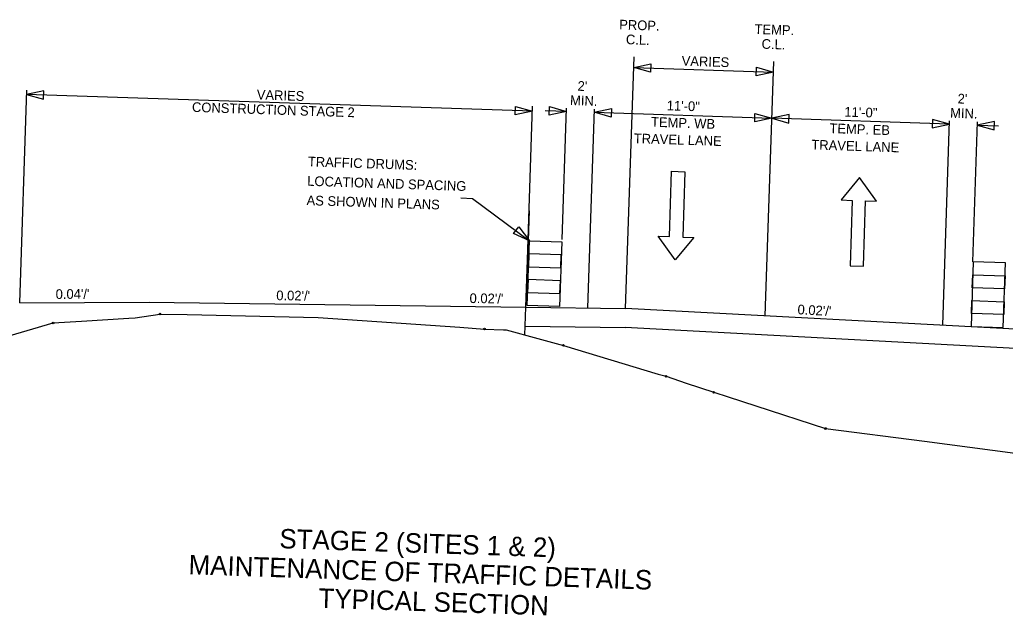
# Model space of a CAD drawing. Extents: x 977258 to 978774, y 1525946 to 1526932.
# Drawn here: x 977645 to 978255, y 1526544 to 1526912 of the extents above; entities that cross this region are included whole.
import ezdxf

# ---------------------------------------------------------------- set-up
doc = ezdxf.new("R2010")
doc.units = 0
for name, color, linetype in [('B_border', 7, 'Continuous'), ('B_County and Route', 7, 'Continuous'), ('B_Preliminary', 7, 'Continuous'), ('B_Print_Date_Text', 7, 'Continuous'), ('B_Title Text', 7, 'Continuous'), ('Default', 7, 'Continuous'), ('R_Border', 7, 'Continuous'), ('R_MOT', 7, 'Continuous'), ('STAMP_PP', 7, 'Continuous')]:
    doc.layers.add(name, color=color, linetype=linetype)

msp = doc.modelspace()

# ---------------------------------------------------------------- linework, layer by layer
at = {"layer": 'B_border'}
for centre in [(977731.73, 1526730.1), (977665.58, 1526724.58), (977932.64, 1526720.78), (977981.46, 1526710.71), (978045.03, 1526691.56), (978074.48, 1526681.68), (978143.72, 1526659.23)]:
    msp.add_circle(centre, 0.5, dxfattribs=at)
at = {"layer": 'B_County and Route'}
for p, q in [((978019.99, 1526733.59), (978025.19, 1526889.28)), ((978106.44, 1526728.97), (978111.69, 1526886.4))]:
    msp.add_line(p, q, dxfattribs=at)
at = {"layer": 'B_Preliminary'}
msp.add_lwpolyline([(977258.38, 1526671.55), (977476.71, 1526670.18), (977576.91, 1526698.71), (977584.62, 1526700.89), (977590.5, 1526702.57), (977665.58, 1526724.58), (977683.24, 1526725.62), (977712.46, 1526727.47), (977716.28, 1526727.8), (977731.73, 1526730.1), (977748.57, 1526729.75), (977829.7, 1526727.99), (977917.45, 1526721.89), (977932.64, 1526720.78), (977944.35, 1526720.32), (977945.99, 1526720.26), (977965.72, 1526714.93), (977981.46, 1526710.71), (978040.15, 1526692.86), (978045.03, 1526691.56), (978057.39, 1526687.35), (978143.72, 1526659.23), (978205.08, 1526651.49), (978261.1, 1526644)], dxfattribs=at)
at = {"layer": 'B_Print_Date_Text'}
for p, q in [((977644.9, 1526736.99), (977724.96, 1526737.52)), ((977724.96, 1526737.52), (977958.24, 1526734.41)), ((977957.66, 1526717.11), (977958.24, 1526734.41)), ((977958.24, 1526734.41), (978019.99, 1526733.59)), ((978314.63, 1526717.86), (978019.99, 1526733.59)), ((977957.84, 1526722.48), (978019.6, 1526721.66)), ((978464.53, 1526697.9), (978019.6, 1526721.66))]:
    msp.add_line(p, q, dxfattribs=at)
at = {"layer": 'B_Title Text'}
for p, q in [((977959.22, 1526763.88), (977960.22, 1526793.85)), ((977960.22, 1526793.85), (977959.41, 1526769.48))]:
    msp.add_line(p, q, dxfattribs=at)
at = {"layer": 'Default'}
for points in [[(978062.22, 1526777.51), (978050.75, 1526763.6), (978040.23, 1526778.24), (978047.1, 1526778.01), (978048.45, 1526818.45), (978056.7, 1526818.17), (978055.35, 1526777.74)], [(978175.36, 1526799.93), (978164.84, 1526814.57), (978153.37, 1526800.66), (978160.24, 1526800.43), (978158.89, 1526760), (978167.14, 1526759.72), (978168.48, 1526800.16)]]:
    msp.add_lwpolyline(points, close=True, dxfattribs=at)
at = {"layer": 'R_MOT'}
for points in [[(977979.06, 1526734.71), (977959.07, 1526735.38), (977960.41, 1526775.36), (977980.4, 1526774.69)], [(977980.13, 1526766.69), (977960.14, 1526767.36), (977959.87, 1526759.37), (977979.86, 1526758.7)], [(978233.79, 1526722.41), (978253.78, 1526721.74), (978255.12, 1526761.72), (978235.13, 1526762.38)], [(977979.6, 1526750.7), (977959.61, 1526751.37), (977959.34, 1526743.37), (977979.33, 1526742.71)], [(978234.86, 1526754.39), (978254.85, 1526753.72), (978254.58, 1526745.73), (978234.59, 1526746.39)], [(978234.33, 1526738.4), (978254.32, 1526737.73), (978254.05, 1526729.74), (978234.06, 1526730.4)]]:
    msp.add_lwpolyline(points, close=True, dxfattribs=at)
at = {"layer": 'STAMP_PP'}
for p, q in [((978024.97, 1526882.68), (978111.47, 1526879.8)), ((977644.9, 1526736.99), (977649.29, 1526868.65)), ((977962.28, 1526855.57), (977649.2, 1526866.01)), ((977983.37, 1526855.48), (977970.14, 1526855.92)), ((977980.73, 1526776.24), (977983.44, 1526857.51)), ((977996.55, 1526733.9), (978000.65, 1526856.93)), ((978000.58, 1526854.91), (978110.52, 1526851.24)), ((978220.46, 1526847.57), (978110.52, 1526851.24)), ((978216.31, 1526723.11), (978220.53, 1526849.6)), ((978234.85, 1526762.39), (978237.74, 1526849.03)), ((978237.67, 1526847), (978250.9, 1526846.56)), ((977918, 1526801.91), (977925.21, 1526801.67)), ((977925.21, 1526801.67), (977960.41, 1526775.36))]:
    msp.add_line(p, q, dxfattribs=at)
for points in [[(978035.43, 1526879.69), (978024.97, 1526882.68), (978035.61, 1526884.97)], [(978101.01, 1526882.79), (978111.47, 1526879.8), (978100.83, 1526877.51)], [(977659.84, 1526868.3), (977649.2, 1526866.01), (977659.67, 1526863.02)], [(977951.81, 1526858.56), (977962.28, 1526855.57), (977951.64, 1526853.29)], [(977972.91, 1526858.47), (977983.37, 1526855.48), (977972.73, 1526853.19)], [(978011.05, 1526851.92), (978000.58, 1526854.91), (978011.22, 1526857.19)], [(978100.05, 1526854.23), (978110.52, 1526851.24), (978099.88, 1526848.95)], [(978121.16, 1526853.53), (978110.52, 1526851.24), (978120.99, 1526848.25)], [(978209.82, 1526845.29), (978220.46, 1526847.57), (978209.99, 1526850.57)], [(978248.31, 1526849.29), (978237.67, 1526847), (978248.13, 1526844.01)], [(977953.83, 1526784.03), (977960.41, 1526775.36), (977950.52, 1526779.91)]]:
    msp.add_lwpolyline(points, close=True, dxfattribs=at)
msp.add_lwpolyline([(977958.24, 1526734.41), (977959.21, 1526763.69), (977962.39, 1526858.82)], dxfattribs=at)

# ---------------------------------------------------------------- texts
at = {"layer": 'R_Border'}
for s, height, rotation, p in [('PROP.', 6, 358.09005, (978015.95, 1526906.24)), ('TEMP.', 6, 358.09005, (978099.71, 1526903.45)), ('C.L.', 6, 358.09005, (978020.09, 1526897.1)), ('C.L.', 6, 358.09005, (978104.08, 1526894.3)), ('VARIES', 6, 358.09005, (978054.61, 1526883.84)), ("2'", 6, 358.09005, (977990.15, 1526868.28)), ('VARIES', 6, 358.09005, (977791.58, 1526862.89)), ('CONSTRUCTION STAGE 2', 6, 358.09005, (977751.48, 1526855.22)), ('MIN.', 6, 358.09005, (977985.51, 1526859.43)), ('11\'-0"', 6, 358.09005, (978045.37, 1526856.2)), ("2'", 6, 358.09005, (978225.43, 1526860.43)), ('11\'-0"', 6, 358.09005, (978155.3, 1526852.29)), ('MIN.', 6, 358.09005, (978220.78, 1526851.58)), ('TEMP. WB', 6, 358.09005, (978035.63, 1526846.02)), ('TEMP. EB', 6, 358.09005, (978146.08, 1526842.09)), ('TRAVEL LANE', 6, 358.09005, (978024.96, 1526835.87)), ('TRAVEL LANE', 6, 358.09005, (978134.89, 1526831.96)), ('TRAFFIC DRUMS:', 6, 358.09005, (977823.21, 1526821.5)), ('LOCATION AND SPACING ', 6, 358.09005, (977822.81, 1526809.5)), ('AS SHOWN IN PLANS', 6, 358.09005, (977822.41, 1526797.51)), ("0.04'/'", 6, 0.38066, (977667.17, 1526739.43)), ("0.02'/'", 6, 359.23582, (977803.7, 1526738.65)), ("0.02'/'", 6, 359.23582, (977923.35, 1526736.92)), ("0.02'/'", 6, 356.94429, (978126.28, 1526729.99)), ('STAGE 2 (SITES 1 & 2)', 12, 358.09005, (977805.51, 1526585.21)), ('MAINTENANCE OF TRAFFIC DETAILS', 12, 358.09005, (977749.29, 1526569.07)), ('TYPICAL SECTION ', 12, 358.09005, (977829.66, 1526548.38))]:
    msp.add_text(s, height=height, rotation=rotation, dxfattribs=at).set_placement(p)

doc.saveas('drawing.dxf')
